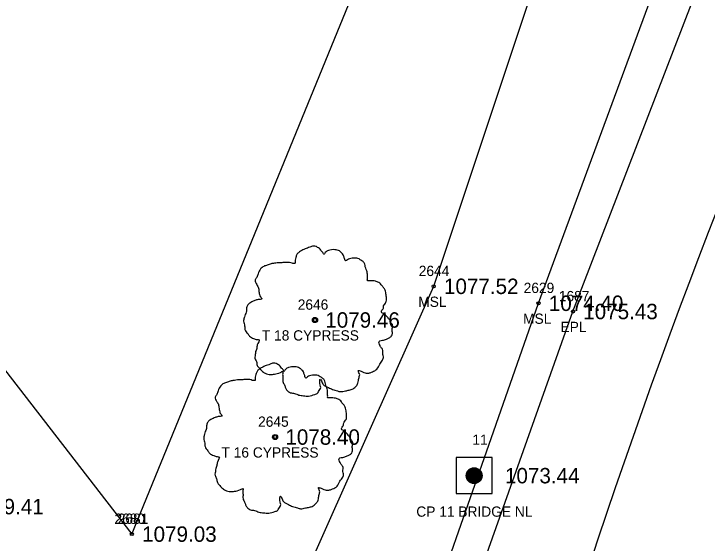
# Model space of a CAD drawing. Extents: x 1578957 to 1581675, y 1115963 to 1120391.
# Drawn here: x 1580542.9 to 1580610.3, y 1119025.4 to 1119076.9 of the extents above; entities that cross this region are included whole.
import ezdxf

# ---------------------------------------------------------------- set-up
doc = ezdxf.new("R2010")
doc.units = 0
for name, color, linetype in [('RD_EX_Fence_Other', 7, 'Continuous'), ('RD_EX_Fence_Other_txCode', 7, 'Continuous'), ('RD_EX_Misc', 7, 'Continuous'), ('RD_EX_Misc_txCode', 7, 'Continuous'), ('RD_EX_Road', 7, 'Continuous'), ('RD_EX_Road_txCode', 7, 'Continuous'), ('RD_EX_TX_Fence_Other_ELEV', 7, 'Continuous'), ('RD_EX_TX_Misc_ELEV', 7, 'Continuous'), ('RD_EX_TX_Road_ELEV', 7, 'Continuous'), ('RD_EX_TX_VEG_ELEV', 7, 'Continuous'), ('RD_EX_VEG', 7, 'Continuous'), ('RD_EX_VEG_txCode', 7, 'Continuous'), ('RD_HC_Cl', 7, 'Continuous'), ('RD_HC_Survey', 7, 'Continuous'), ('RD_HC_Survey_ELEV', 7, 'Continuous'), ('RD_HC_Survey_txCode', 7, 'Continuous'), ('RD_SMD_Locator', 7, 'Continuous')]:
    doc.layers.add(name, color=color, linetype=linetype)

msp = doc.modelspace()

# ---------------------------------------------------------------- linework, layer by layer
at = {"layer": 'RD_EX_Fence_Other'}
msp.add_lwpolyline([(1580513.827, 1119078.662), (1580554.331, 1119026.263), (1580554.331, 1119026.263), (1580661.056, 1119287.238), (1580681.048, 1119334.68), (1580698.952, 1119378.888), (1580718.027, 1119424.961), (1580737.744, 1119473.232)], dxfattribs=at)
at = {"layer": 'RD_EX_Misc'}
for points in [[(1580575.469, 1119001.964), (1580572.192, 1119003.299), (1580573.344, 1119008.973), (1580569.078, 1119017.528), (1580583.69, 1119050.381), (1580599.817, 1119098.808), (1580624.045, 1119165.829), (1580641.396, 1119195.473), (1580666.371, 1119238.149), (1580687.021, 1119280.073), (1580703.349, 1119329.398), (1580719.477, 1119374.249), (1580736.36, 1119422.972), (1580751.158, 1119471.49)], [(1580572.228, 1119003.293), (1580577.641, 1119002.275), (1580593.887, 1119048.73), (1580611.465, 1119096.441), (1580629.396, 1119141.91), (1580650.31, 1119188.617), (1580669.532, 1119232.972), (1580689.078, 1119279.767), (1580706.148, 1119326.435), (1580722.862, 1119373.532), (1580740.07, 1119420.2), (1580755.304, 1119467.381)]]:
    msp.add_lwpolyline(points, dxfattribs=at)
at = {"layer": 'RD_EX_Road'}
msp.add_lwpolyline([(1580561.509, 1118902.856), (1580569.284, 1118952.033), (1580572.257, 1118964.729), (1580572.024, 1118971.684), (1580570.785, 1118976.943), (1580576.68, 1118999.159), (1580578.916, 1119000.71), (1580583.17, 1119008.339), (1580597.232, 1119047.928), (1580615.21, 1119094.659), (1580634.106, 1119140.594), (1580653.543, 1119186.411), (1580672.941, 1119232.27), (1580691.817, 1119278.399), (1580709.783, 1119324.767), (1580727.167, 1119371.358), (1580744.517, 1119418.33), (1580760.444, 1119465.683)], dxfattribs=at)
at = {"layer": 'RD_EX_VEG'}
for centre, radius in [((1580572.144, 1119047.104), 0.25), ((1580572.131, 1119047.085), 0.0001), ((1580568.264, 1119035.711), 0.25), ((1580568.252, 1119035.692), 0.0001)]:
    msp.add_circle(centre, radius, dxfattribs=at)
for points in [[(1580572.276, 1119054.272), (1580571.976, 1119054.297), (1580571.651, 1119054.197), (1580571.401, 1119054.097), (1580571.176, 1119054.022), (1580570.951, 1119053.922), (1580570.651, 1119053.747), (1580570.426, 1119053.547), (1580570.301, 1119053.297), (1580570.251, 1119053.072), (1580570.202, 1119052.797), (1580570.202, 1119052.622), (1580570.077, 1119052.597), (1580569.927, 1119052.622), (1580569.677, 1119052.697), (1580569.427, 1119052.697), (1580569.177, 1119052.697), (1580568.827, 1119052.672), (1580568.477, 1119052.672), (1580568.202, 1119052.622), (1580567.878, 1119052.572), (1580567.503, 1119052.447), (1580567.153, 1119052.322), (1580566.853, 1119052.072), (1580566.603, 1119051.598), (1580566.478, 1119051.248), (1580566.328, 1119050.998), (1580566.478, 1119050.548), (1580566.653, 1119050.198), (1580566.678, 1119049.998), (1580566.753, 1119049.574), (1580566.853, 1119049.349), (1580566.978, 1119049.149), (1580566.903, 1119049.124), (1580566.528, 1119049.074), (1580566.228, 1119048.974), (1580565.803, 1119048.749), (1580565.579, 1119048.524), (1580565.479, 1119048.199), (1580565.454, 1119047.849), (1580565.354, 1119047.649), (1580565.279, 1119047.375), (1580565.254, 1119047.3), (1580565.204, 1119046.975), (1580565.304, 1119046.525), (1580565.329, 1119046.175), (1580565.454, 1119045.95), (1580565.604, 1119045.775), (1580565.778, 1119045.525), (1580566.178, 1119045.3), (1580566.503, 1119045.2), (1580566.703, 1119045.176), (1580566.528, 1119044.676), (1580566.478, 1119044.326), (1580566.353, 1119043.926), (1580566.353, 1119043.851), (1580566.303, 1119043.376), (1580566.453, 1119043.051), (1580566.528, 1119042.677), (1580566.703, 1119042.452), (1580566.978, 1119042.152), (1580567.303, 1119041.927), (1580567.803, 1119041.802), (1580568.202, 1119041.827), (1580568.777, 1119042.002), (1580569.027, 1119042.077), (1580569.002, 1119041.902), (1580569.027, 1119041.527), (1580569.027, 1119041.102), (1580569.177, 1119040.777), (1580569.277, 1119040.503), (1580569.427, 1119040.253), (1580569.752, 1119040.028), (1580570.152, 1119039.953), (1580570.576, 1119039.803), (1580571.026, 1119039.728), (1580571.526, 1119039.703), (1580572.126, 1119039.853), (1580572.401, 1119039.978), (1580572.501, 1119040.153), (1580572.7, 1119040.528), (1580572.65, 1119040.752), (1580572.675, 1119041.352), (1580572.775, 1119041.177), (1580572.95, 1119040.827), (1580573.45, 1119040.528), (1580573.85, 1119040.353), (1580574.325, 1119040.203), (1580574.625, 1119040.128), (1580575.099, 1119040.203), (1580575.474, 1119040.278), (1580575.849, 1119040.403), (1580576.149, 1119040.677), (1580576.324, 1119040.952), (1580576.374, 1119041.227), (1580576.449, 1119041.602), (1580576.499, 1119041.777)], [(1580576.499, 1119041.777), (1580576.424, 1119041.952), (1580576.374, 1119042.202), (1580576.449, 1119042.177), (1580576.624, 1119042.127), (1580576.899, 1119042.002), (1580577.124, 1119041.927), (1580577.448, 1119041.952), (1580577.723, 1119042.052), (1580578.173, 1119042.327), (1580578.448, 1119042.802), (1580578.723, 1119043.201), (1580578.798, 1119043.526), (1580578.748, 1119043.751), (1580578.723, 1119044.251), (1580578.523, 1119044.501), (1580578.473, 1119044.626), (1580578.373, 1119045.026), (1580578.448, 1119045.076), (1580578.723, 1119045.126), (1580579.098, 1119045.25), (1580579.373, 1119045.375), (1580579.597, 1119045.55), (1580579.672, 1119045.775), (1580579.647, 1119046.175), (1580579.697, 1119046.575), (1580579.622, 1119046.725), (1580579.522, 1119046.875), (1580579.447, 1119047.075), (1580579.298, 1119047.225), (1580579.198, 1119047.375), (1580579.098, 1119047.474), (1580578.973, 1119047.624), (1580578.798, 1119047.749), (1580578.648, 1119047.799), (1580578.598, 1119047.949), (1580578.748, 1119048.149), (1580578.798, 1119048.249), (1580578.823, 1119048.474), (1580579.048, 1119048.824), (1580579.098, 1119049.224), (1580579.048, 1119049.649), (1580578.998, 1119049.923), (1580578.848, 1119050.198), (1580578.648, 1119050.448), (1580578.523, 1119050.623), (1580578.348, 1119050.748), (1580578.023, 1119050.873), (1580577.773, 1119050.923), (1580577.423, 1119050.923), (1580577.223, 1119050.973), (1580577.248, 1119051.023), (1580577.248, 1119051.173), (1580577.248, 1119051.448), (1580577.173, 1119051.898), (1580577.024, 1119052.397), (1580577.024, 1119052.422), (1580576.924, 1119052.672), (1580576.699, 1119052.872), (1580576.524, 1119052.972), (1580576.324, 1119053.097), (1580576.074, 1119053.122), (1580575.774, 1119053.122), (1580575.499, 1119053.072), (1580575.299, 1119052.972), (1580575.124, 1119052.847), (1580575.049, 1119052.997), (1580574.949, 1119053.297), (1580574.899, 1119053.447), (1580574.75, 1119053.622), (1580574.525, 1119053.822), (1580574.075, 1119053.947), (1580573.45, 1119053.872), (1580573.15, 1119053.672), (1580573, 1119053.497), (1580572.95, 1119053.622), (1580572.75, 1119053.822), (1580572.65, 1119053.997), (1580572.476, 1119054.122), (1580572.326, 1119054.222), (1580572.226, 1119054.272)], [(1580568.396, 1119042.878), (1580568.096, 1119042.903), (1580567.771, 1119042.803), (1580567.521, 1119042.703), (1580567.297, 1119042.628), (1580567.072, 1119042.528), (1580566.772, 1119042.353), (1580566.547, 1119042.153), (1580566.422, 1119041.903), (1580566.372, 1119041.678), (1580566.322, 1119041.403), (1580566.322, 1119041.228), (1580566.197, 1119041.203), (1580566.047, 1119041.228), (1580565.797, 1119041.303), (1580565.547, 1119041.303), (1580565.297, 1119041.303), (1580564.948, 1119041.278), (1580564.598, 1119041.278), (1580564.323, 1119041.228), (1580563.998, 1119041.179), (1580563.623, 1119041.054), (1580563.273, 1119040.929), (1580562.973, 1119040.679), (1580562.724, 1119040.204), (1580562.599, 1119039.854), (1580562.449, 1119039.604), (1580562.599, 1119039.154), (1580562.774, 1119038.805), (1580562.798, 1119038.605), (1580562.873, 1119038.18), (1580562.973, 1119037.955), (1580563.098, 1119037.755), (1580563.023, 1119037.73), (1580562.649, 1119037.68), (1580562.349, 1119037.58), (1580561.924, 1119037.355), (1580561.699, 1119037.13), (1580561.599, 1119036.805), (1580561.574, 1119036.456), (1580561.474, 1119036.256), (1580561.399, 1119035.981), (1580561.374, 1119035.906), (1580561.324, 1119035.581), (1580561.424, 1119035.131), (1580561.449, 1119034.781), (1580561.574, 1119034.556), (1580561.724, 1119034.382), (1580561.899, 1119034.132), (1580562.299, 1119033.907), (1580562.624, 1119033.807), (1580562.823, 1119033.782), (1580562.649, 1119033.282), (1580562.599, 1119032.932), (1580562.474, 1119032.532), (1580562.474, 1119032.457), (1580562.424, 1119031.983), (1580562.574, 1119031.658), (1580562.649, 1119031.283), (1580562.823, 1119031.058), (1580563.098, 1119030.758), (1580563.423, 1119030.533), (1580563.923, 1119030.408), (1580564.323, 1119030.433), (1580564.898, 1119030.608), (1580565.147, 1119030.683), (1580565.122, 1119030.508), (1580565.147, 1119030.133), (1580565.147, 1119029.709), (1580565.297, 1119029.384), (1580565.397, 1119029.109), (1580565.547, 1119028.859), (1580565.872, 1119028.634), (1580566.272, 1119028.559), (1580566.697, 1119028.409), (1580567.147, 1119028.334), (1580567.646, 1119028.309), (1580568.246, 1119028.459), (1580568.521, 1119028.584), (1580568.621, 1119028.759), (1580568.821, 1119029.134), (1580568.771, 1119029.359), (1580568.796, 1119029.958), (1580568.896, 1119029.783), (1580569.071, 1119029.434), (1580569.571, 1119029.134), (1580569.97, 1119028.959), (1580570.445, 1119028.809), (1580570.745, 1119028.734), (1580571.22, 1119028.809), (1580571.595, 1119028.884), (1580571.969, 1119029.009), (1580572.269, 1119029.284), (1580572.444, 1119029.559), (1580572.494, 1119029.833), (1580572.569, 1119030.208), (1580572.619, 1119030.383)], [(1580572.619, 1119030.383), (1580572.544, 1119030.558), (1580572.494, 1119030.808), (1580572.569, 1119030.783), (1580572.744, 1119030.733), (1580573.019, 1119030.608), (1580573.244, 1119030.533), (1580573.569, 1119030.558), (1580573.844, 1119030.658), (1580574.293, 1119030.933), (1580574.568, 1119031.408), (1580574.843, 1119031.808), (1580574.918, 1119032.132), (1580574.868, 1119032.357), (1580574.843, 1119032.857), (1580574.643, 1119033.107), (1580574.593, 1119033.232), (1580574.493, 1119033.632), (1580574.568, 1119033.682), (1580574.843, 1119033.732), (1580575.218, 1119033.857), (1580575.493, 1119033.982), (1580575.718, 1119034.157), (1580575.793, 1119034.382), (1580575.768, 1119034.781), (1580575.818, 1119035.181), (1580575.743, 1119035.331), (1580575.643, 1119035.481), (1580575.568, 1119035.681), (1580575.418, 1119035.831), (1580575.318, 1119035.981), (1580575.218, 1119036.081), (1580575.093, 1119036.231), (1580574.918, 1119036.356), (1580574.768, 1119036.406), (1580574.718, 1119036.556), (1580574.868, 1119036.755), (1580574.918, 1119036.855), (1580574.943, 1119037.08), (1580575.168, 1119037.43), (1580575.218, 1119037.83), (1580575.168, 1119038.255), (1580575.118, 1119038.53), (1580574.968, 1119038.805), (1580574.768, 1119039.054), (1580574.643, 1119039.229), (1580574.468, 1119039.354), (1580574.144, 1119039.479), (1580573.894, 1119039.529), (1580573.544, 1119039.529), (1580573.344, 1119039.579), (1580573.369, 1119039.629), (1580573.369, 1119039.779), (1580573.369, 1119040.054), (1580573.294, 1119040.504), (1580573.144, 1119041.004), (1580573.144, 1119041.029), (1580573.044, 1119041.278), (1580572.819, 1119041.478), (1580572.644, 1119041.578), (1580572.444, 1119041.703), (1580572.194, 1119041.728), (1580571.895, 1119041.728), (1580571.62, 1119041.678), (1580571.42, 1119041.578), (1580571.245, 1119041.453), (1580571.17, 1119041.603), (1580571.07, 1119041.903), (1580571.02, 1119042.053), (1580570.87, 1119042.228), (1580570.645, 1119042.428), (1580570.195, 1119042.553), (1580569.571, 1119042.478), (1580569.271, 1119042.278), (1580569.121, 1119042.103), (1580569.071, 1119042.228), (1580568.871, 1119042.428), (1580568.771, 1119042.603), (1580568.596, 1119042.728), (1580568.446, 1119042.828), (1580568.346, 1119042.878)]]:
    msp.add_spline(points, degree=3, dxfattribs=at)
at = {"layer": 'RD_HC_Cl'}
msp.add_arc((1581224.951, 1118817.811), 658.967, 157.467285, 172.167204, dxfattribs=at)
at = {"layer": 'RD_HC_Survey'}
for p, q in [((1580586.947, 1119031.583), (1580586.947, 1119032.325)), ((1580586.972, 1119031.541), (1580586.972, 1119032.367)), ((1580586.997, 1119031.504), (1580586.997, 1119032.403)), ((1580587.022, 1119031.472), (1580587.022, 1119032.436)), ((1580587.046, 1119031.443), (1580587.046, 1119032.465)), ((1580587.071, 1119031.416), (1580587.071, 1119032.492)), ((1580587.096, 1119031.392), (1580587.096, 1119032.516)), ((1580587.121, 1119031.37), (1580587.121, 1119032.538)), ((1580587.145, 1119031.349), (1580587.145, 1119032.558)), ((1580587.17, 1119031.331), (1580587.17, 1119032.577)), ((1580587.195, 1119031.313), (1580587.195, 1119032.594)), ((1580587.22, 1119031.298), (1580587.22, 1119032.61)), ((1580587.244, 1119031.283), (1580587.244, 1119032.625)), ((1580587.269, 1119031.27), (1580587.269, 1119032.638)), ((1580587.294, 1119031.258), (1580587.294, 1119032.65)), ((1580587.319, 1119031.246), (1580587.319, 1119032.661)), ((1580587.343, 1119031.236), (1580587.343, 1119032.671)), ((1580587.368, 1119031.227), (1580587.368, 1119032.68)), ((1580587.393, 1119031.219), (1580587.393, 1119032.689)), ((1580587.418, 1119031.212), (1580587.418, 1119032.696)), ((1580587.442, 1119031.205), (1580587.442, 1119032.702)), ((1580587.467, 1119031.2), (1580587.467, 1119032.708)), ((1580587.492, 1119031.195), (1580587.492, 1119032.712)), ((1580587.517, 1119031.192), (1580587.517, 1119032.716)), ((1580587.541, 1119031.189), (1580587.541, 1119032.719)), ((1580587.566, 1119031.186), (1580587.566, 1119032.721)), ((1580587.591, 1119031.185), (1580587.591, 1119032.723)), ((1580587.616, 1119031.184), (1580587.616, 1119032.723)), ((1580587.64, 1119031.185), (1580587.64, 1119032.723)), ((1580587.665, 1119031.186), (1580587.665, 1119032.722)), ((1580587.69, 1119031.187), (1580587.69, 1119032.72)), ((1580587.715, 1119031.19), (1580587.715, 1119032.718)), ((1580587.739, 1119031.193), (1580587.739, 1119032.714)), ((1580587.764, 1119031.198), (1580587.764, 1119032.71)), ((1580587.789, 1119031.203), (1580587.789, 1119032.705)), ((1580587.814, 1119031.209), (1580587.814, 1119032.699)), ((1580587.838, 1119031.216), (1580587.838, 1119032.692)), ((1580587.863, 1119031.223), (1580587.863, 1119032.684)), ((1580587.888, 1119031.232), (1580587.888, 1119032.676)), ((1580587.913, 1119031.242), (1580587.913, 1119032.666)), ((1580587.937, 1119031.252), (1580587.937, 1119032.655)), ((1580587.962, 1119031.264), (1580587.962, 1119032.644)), ((1580587.987, 1119031.277), (1580587.987, 1119032.631)), ((1580588.012, 1119031.291), (1580588.012, 1119032.617)), ((1580588.036, 1119031.306), (1580588.036, 1119032.602)), ((1580588.061, 1119031.322), (1580588.061, 1119032.585)), ((1580588.086, 1119031.34), (1580588.086, 1119032.567)), ((1580588.111, 1119031.36), (1580588.111, 1119032.548)), ((1580588.135, 1119031.381), (1580588.135, 1119032.527)), ((1580588.16, 1119031.404), (1580588.16, 1119032.503)), ((1580588.185, 1119031.43), (1580588.185, 1119032.478)), ((1580588.21, 1119031.458), (1580588.21, 1119032.45)), ((1580588.234, 1119031.488), (1580588.234, 1119032.419)), ((1580588.259, 1119031.523), (1580588.259, 1119032.385)), ((1580588.284, 1119031.562), (1580588.284, 1119032.345)), ((1580586.873, 1119031.775), (1580586.873, 1119032.133)), ((1580586.898, 1119031.692), (1580586.898, 1119032.216)), ((1580586.923, 1119031.632), (1580586.923, 1119032.276)), ((1580588.309, 1119031.607), (1580588.309, 1119032.3)), ((1580588.333, 1119031.662), (1580588.333, 1119032.246)), ((1580588.358, 1119031.731), (1580588.358, 1119032.176)), ((1580588.383, 1119031.842), (1580588.383, 1119032.066))]:
    msp.add_line(p, q, dxfattribs=at)
msp.add_lwpolyline([(1580589.372, 1119033.704), (1580585.872, 1119033.704), (1580585.872, 1119030.204), (1580589.372, 1119030.204)], close=True, dxfattribs=at)
msp.add_circle((1580587.622, 1119031.954), 0.769, dxfattribs=at)
at = {"layer": 'RD_SMD_Locator'}
for centre in [(1580583.69, 1119050.381), (1580593.887, 1119048.73), (1580597.232, 1119047.928), (1580572.144, 1119047.104), (1580568.264, 1119035.711), (1580587.622, 1119031.954), (1580554.331, 1119026.263), (1580554.331, 1119026.263)]:
    msp.add_circle(centre, 0.15, dxfattribs=at)

# ---------------------------------------------------------------- texts
at = {"layer": 'RD_EX_Fence_Other_txCode'}
for s, p in [('2680', (1580552.638, 1119027.263)), ('2681', (1580552.961, 1119027.263))]:
    msp.add_text(s, height=1, dxfattribs=at).set_placement(p)
at = {"layer": 'RD_EX_Misc_txCode'}
for s, p in [('2644', (1580582.238, 1119051.381)), ('2629', (1580592.441, 1119049.73)), ('MSL', (1580582.188, 1119048.381)), ('MSL', (1580592.384, 1119046.73))]:
    msp.add_text(s, height=1, dxfattribs=at).set_placement(p)
at = {"layer": 'RD_EX_Road_txCode'}
for s, p in [('1687', (1580595.861, 1119048.928)), ('EPL', (1580596.027, 1119045.928))]:
    msp.add_text(s, height=1, dxfattribs=at).set_placement(p)
at = {"layer": 'RD_EX_TX_Fence_Other_ELEV'}
msp.add_text('1079.03', height=1.5, dxfattribs=at).set_placement((1580555.331, 1119025.513))
msp.add_text('1079.03', height=1.5, dxfattribs=at).set_placement((1580555.331, 1119025.513))
at = {"layer": 'RD_EX_TX_Misc_ELEV'}
for s, p in [('1077.52', (1580584.69, 1119049.631)), ('1074.40', (1580594.887, 1119047.98))]:
    msp.add_text(s, height=1.5, dxfattribs=at).set_placement(p)
at = {"layer": 'RD_EX_TX_Road_ELEV'}
msp.add_text('1075.43', height=1.5, dxfattribs=at).set_placement((1580598.232, 1119047.178))
at = {"layer": 'RD_EX_TX_VEG_ELEV'}
for s, p in [('1079.46', (1580573.144, 1119046.354)), ('1078.40', (1580569.264, 1119034.961)), ('1079.41', (1580538.511, 1119028.19))]:
    msp.add_text(s, height=1.5, dxfattribs=at).set_placement(p)
at = {"layer": 'RD_EX_VEG_txCode'}
for s, p in [('2646', (1580570.467, 1119048.104)), ('T 18 CYPRESS', (1580566.978, 1119045.104)), ('2645', (1580566.611, 1119036.711)), ('T 16 CYPRESS', (1580563.052, 1119033.711))]:
    msp.add_text(s, height=1, dxfattribs=at).set_placement(p)
at = {"layer": 'RD_HC_Survey_ELEV'}
msp.add_text('1073.44', height=1.5, dxfattribs=at).set_placement((1580590.622, 1119031.204))
at = {"layer": 'RD_HC_Survey_txCode'}
for s, p in [('11', (1580587.456, 1119034.954)), ('CP 11 BRIDGE NL', (1580582, 1119027.954))]:
    msp.add_text(s, height=1, dxfattribs=at).set_placement(p)

doc.saveas('drawing.dxf')
